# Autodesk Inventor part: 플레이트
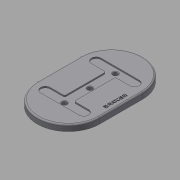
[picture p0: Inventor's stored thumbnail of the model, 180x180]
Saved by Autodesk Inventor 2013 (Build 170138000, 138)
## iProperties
Created: 2016-08
Part Number: 플레이트
Material: 알루미늄 6061
Document SubType Name: Modeling
Designer: mduedu
Density: 2.71 g/cm^3
Author: mduedu
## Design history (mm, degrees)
sketch "스케치1" dims "d0" = 220, "d2" = 130
  geometry: L1 (45, 65)-(-45, 65); L2 (-45, 65)-(-45, -65); L3 (-45, -65)-(45, -65); L4 (45, -65)-(45, 65); L5 (45, 65)-(-45, -65); L6 (-45, 65)-(45, -65); 5 further points
  constraints: 12 end point, 5 midpoint, 2 parallel, 2 vertical alignment, 1 coincident, 1 horizontal, 1 perpendicular, 4 other
extrude "돌출1" new body sketch "스케치1" distance "d3" = 13; taper "d4" = 0 deg
sketch "스케치2"
  geometry: L1 (-63, -50)-(63, -50); L2 (63, -50)-(63, 50); L3 (63, 50)-(-63, 50); L4 (-63, 50)-(-63, -50); L5 (-63, -50)-(63, 50); L6 (63, -50)-(-63, 50); L7 (-63, 50)-(-43, 50); L8 (-43, 50)-(-43, -50); L9 (-43, -50)-(-63, -50); L10 (-63, -50)-(-63, 50); L11 (63, 50)-(43, 50); L12 (43, 50)-(43, -50); L13 (43, -50)-(63, -50); L14 (63, -50)-(63, 50); L15 (-43, -10)-(43, -10); L16 (43, -10)-(43, 10); L17 (43, 10)-(-43, 10); L18 (-43, 10)-(-43, -10); L19 (-43, -10)-(43, 10); L20 (43, -10)-(-43, 10); 1 further point
  constraints: 40 end point, 8 parallel, 4 horizontal, 4 midpoint, 4 perpendicular, 3 point on line
  dimensions: "d18" = 126 distance of L3.end L2.end; "d19" = 100 distance of L2.end L1.end; "d20" = 20 distance of L8.end L9.end; "d21" = 20 distance of L12.end L13.end (= d20); "d22" = 20 distance of L15.end L16.end
extrude "돌출3" cut sketch "스케치2" distance "d23" = 3; taper "d24" = 0 deg
fillet "모깎기2"
fillet "모깎기3"
fillet "모깎기4"
fillet "모깎기5"
fillet "모깎기6" dims "d25" = 3
sketch "스케치4"
  geometry: L1 (-43, -40)-(-43, -13) reference; L2 (-40, -10)-(40, -10) reference; L3 (43, -13)-(43, -40) reference; L4 (63, -40)-(63, 40) reference; L5 (43, 40)-(43, 13) reference; L6 (40, 10)-(-40, 10) reference; L7 (-43, 13)-(-43, 40) reference; L8 (-63, 40)-(-63, -40) reference; L9 (45, -65)-(-45, -65) reference; L10 (-45, 65)-(45, 65) reference; L11 (-53, 40)-(-53, -40); L12 (53, 40)-(53, -40); L13 (-53, 0)-(53, 0); C1 r 5 at (-53, 0); C2 r 5 at (0, 0); C3 r 5 at (53, 0); A1 r 10 centre (-53, -40) between (-63, -40) and (-43, -40) reference; A2 r 3 centre (-40, -13) between (-40, -10) and (-43, -13) reference; A3 r 3 centre (40, -13) between (43, -13) and (40, -10) reference; A4 r 10 centre (53, -40) between (43, -40) and (63, -40) reference; A5 r 10 centre (53, 40) between (63, 40) and (43, 40) reference; A6 r 3 centre (40, 13) between (40, 10) and (43, 13) reference; A7 r 3 centre (-40, 13) between (-43, 13) and (-40, 10) reference; A8 r 10 centre (-53, 40) between (-43, 40) and (-63, 40) reference; A9 r 65 centre (45, 0) between (45, -65) and (45, 65) reference; A10 r 65 centre (-45, 0) between (-45, 65) and (-45, -65) reference; 1 further point
  constraints: 6 end point, 3 centre point, 3 coincident, 2 midpoint, 1 parallel, 1 perpendicular
  dimensions: "d26" = 10 diameter of C1; "d27" = 10 diameter of C2; "d28" = 10 diameter of C3
extrude "돌출4" cut sketch "스케치4" stored distance "d29" = 3; taper "d30" = 0 deg
chamfer "모따기2" distance "d31" = 1; stored, may be unused: second distance "d32" = 2, angle "d33" = 45 deg
fillet "모깎기1" dims "d14" = 3
sketch "스케치3"
  geometry: L1 (-45, -65)-(45, -65) reference; 2 further points
  constraints: 1 vertical alignment, 1 other
  dimensions: "d15" = 12 distance from line of point (0, -53) L1
feature "엠보싱1" sketch "스케치3" dims "d0" = 220, "d2" = 130, "d16" = 0.5, "d17" = 0
node "솔리드1"
node "절단 모서리 투영1"
